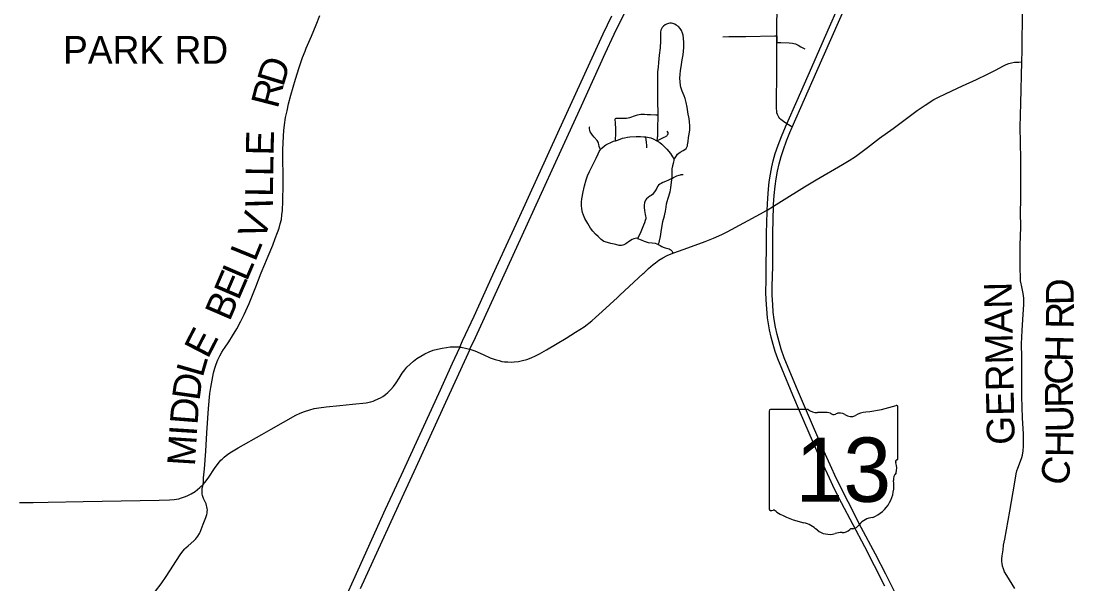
# Model space of a CAD drawing. Extents: x 40529 to 41139, y 15164 to 15584.
# Drawn here: x 40644 to 40708.7, y 15483.8 to 15518.4 of the extents above; entities that cross this region are included whole.
import ezdxf

# ---------------------------------------------------------------- set-up
doc = ezdxf.new("R2010")
doc.units = 0
for name, color, linetype in [('GM_X_County_Road', 7, 'Continuous'), ('GM_X_County_Road_Text', 7, 'Continuous'), ('GM_X_Interstate_Route', 7, 'Continuous'), ('GM_X_State_Route', 7, 'Continuous'), ('GM_X_State_Shield', 7, 'Continuous'), ('GM_X_Township_Road', 7, 'Continuous'), ('GM_X_Township_Road_Text', 7, 'Continuous')]:
    doc.layers.add(name, color=color, linetype=linetype)

msp = doc.modelspace()

# ---------------------------------------------------------------- linework, layer by layer
at = {"layer": 'GM_X_County_Road'}
msp.add_line((40690.484, 15517.074), (40690.486, 15517.482), dxfattribs=at)
for points in [[(40690.486, 15517.482), (40690.499, 15519.736), (40690.48, 15523.462), (40690.467, 15524.818), (40690.446, 15526.018), (40690.447, 15526.289)], [(40690.562, 15512.571), (40690.524, 15512.659), (40690.496, 15512.751), (40690.478, 15512.845), (40690.463, 15513.033), (40690.462, 15513.501), (40690.483, 15515.082), (40690.484, 15517.036), (40690.484, 15517.074)], [(40691.434, 15511.871), (40691.416, 15511.883), (40691.101, 15512.084), (40690.889, 15512.219), (40690.735, 15512.343), (40690.669, 15512.412), (40690.611, 15512.488), (40690.562, 15512.571)], [(40690.285, 15507.02), (40690.287, 15507.118), (40690.319, 15507.677), (40690.374, 15508.235), (40690.437, 15508.698), (40690.52, 15509.158), (40690.624, 15509.613), (40690.748, 15510.063), (40690.89, 15510.508), (40691.083, 15511.034), (40691.294, 15511.552), (40691.434, 15511.871)], [(40697.852, 15483.037), (40697.191, 15484.373), (40696.554, 15485.617), (40695.678, 15487.262), (40694.865, 15488.835), (40694.158, 15490.253), (40693.761, 15491.096), (40693.263, 15492.201), (40692.676, 15493.571), (40691.766, 15495.715), (40691.183, 15497.088), (40690.943, 15497.696), (40690.757, 15498.224), (40690.62, 15498.67), (40690.501, 15499.122), (40690.403, 15499.578), (40690.326, 15500.039), (40690.27, 15500.502), (40690.232, 15500.967), (40690.209, 15501.527), (40690.205, 15502.087), (40690.235, 15503.298), (40690.25, 15505.348), (40690.285, 15507.02)]]:
    msp.add_lwpolyline(points, dxfattribs=at)
at = {"layer": 'GM_X_Interstate_Route'}
for points in [[(40664.908, 15483.496), (40667.468, 15489.094), (40668.323, 15490.959), (40670.372, 15495.457), (40671.634, 15498.213), (40671.653, 15498.253), (40671.967, 15498.932), (40673.396, 15502.073), (40674.83, 15505.21), (40677, 15509.96), (40678.476, 15513.18), (40679.946, 15516.404), (40680.496, 15517.588), (40680.984, 15518.596), (40681.489, 15519.595), (40682.099, 15520.751), (40682.591, 15521.651), (40683.149, 15522.622), (40683.815, 15523.746), (40684.402, 15524.699), (40684.957, 15525.562), (40685.445, 15526.292)], [(40663.802, 15482.52), (40664.754, 15484.647), (40665.607, 15486.512), (40666.451, 15488.381), (40667.424, 15490.498), (40669.714, 15495.498), (40670.562, 15497.365), (40671.003, 15498.331), (40671.012, 15498.352), (40671.181, 15498.722), (40671.88, 15500.248), (40673.036, 15502.793), (40673.858, 15504.569), (40674.592, 15506.181), (40677.027, 15511.523), (40679.237, 15516.354), (40679.823, 15517.622), (40680.352, 15518.712)]]:
    msp.add_lwpolyline(points, dxfattribs=at)
at = {"layer": 'GM_X_State_Route'}
for points in [[(40691.434, 15511.871), (40692.936, 15515.309), (40694.748, 15519.398), (40695.416, 15520.936), (40696.278, 15522.898), (40696.671, 15523.843), (40697.323, 15525.488), (40697.886, 15526.968), (40699.808, 15532.115), (40700.334, 15533.519), (40701.168, 15535.797)], [(40697.124, 15483.649), (40696.496, 15484.899), (40695.887, 15486.053), (40694.461, 15488.777), (40694.038, 15489.606), (40693.72, 15490.28), (40692.952, 15491.977), (40691.95, 15494.284), (40691.468, 15495.394), (40690.788, 15497.029), (40690.549, 15497.634), (40690.393, 15498.072), (40690.255, 15498.516), (40690.135, 15498.964), (40690.033, 15499.417), (40689.967, 15499.783), (40689.918, 15500.151), (40689.865, 15500.706), (40689.832, 15501.263), (40689.82, 15501.728), (40689.827, 15502.473), (40689.861, 15505.361), (40689.893, 15506.665), (40689.897, 15506.776), (40689.924, 15507.502), (40689.966, 15508.058), (40690.018, 15508.52), (40690.088, 15508.98), (40690.176, 15509.436), (40690.263, 15509.797), (40690.394, 15510.243), (40690.572, 15510.772), (40690.769, 15511.294), (40691.019, 15511.896), (40691.101, 15512.084), (40691.728, 15513.517), (40692.627, 15515.565), (40693.42, 15517.354), (40694.508, 15519.826)], [(40690.285, 15507.02), (40690.287, 15507.118), (40690.319, 15507.677), (40690.374, 15508.235), (40690.437, 15508.698), (40690.52, 15509.158), (40690.624, 15509.613), (40690.748, 15510.063), (40690.89, 15510.508), (40691.083, 15511.034), (40691.294, 15511.552), (40691.434, 15511.871)], [(40697.852, 15483.037), (40697.191, 15484.373), (40696.554, 15485.617), (40695.678, 15487.262), (40694.865, 15488.835), (40694.158, 15490.253), (40693.761, 15491.096), (40693.263, 15492.201), (40692.676, 15493.571), (40691.766, 15495.715), (40691.183, 15497.088), (40690.943, 15497.696), (40690.757, 15498.224), (40690.62, 15498.67), (40690.501, 15499.122), (40690.403, 15499.578), (40690.326, 15500.039), (40690.27, 15500.502), (40690.232, 15500.967), (40690.209, 15501.527), (40690.205, 15502.087), (40690.235, 15503.298), (40690.25, 15505.348), (40690.285, 15507.02)]]:
    msp.add_lwpolyline(points, dxfattribs=at)
at = {"layer": 'GM_X_State_Shield'}
for p, q in [((40690.017, 15494.411), (40690.017, 15488.408)), ((40692.412, 15494.515), (40690.095, 15494.515)), ((40697.927, 15491.523), (40697.927, 15494.664)), ((40697.927, 15491.524), (40697.927, 15491.523))]:
    msp.add_line(p, q, dxfattribs=at)
for centre, radius, start, end in [((40690.108, 15494.424), 0.0916, 98.1301, 188.1301), ((40692.963, 15495.212), 0.889, 231.61951, 271.11188), ((40696.18, 15492.681), 1.688, 97.34618, 120.76885), ((40695.11, 15502.7), 8.388, 275.84447, 288.90645), ((40697.84, 15494.677), 0.0881, 351.86209, 97.738), ((40693.258, 15491.144), 3.191, 80.48669, 94.98827), ((40693.983, 15494.455), 0.256, 219.79206, 297.10237), ((40694.359, 15493.761), 0.533, 54.46668, 119.14113), ((40695.047, 15494.713), 0.641, 233.85621, 294.82819), ((40697.907, 15491.292), 0.136, 107.94398, 210.33697), ((40697.04, 15490.895), 0.818, 340.03296, 23.64957), ((40697.833, 15491.511), 0.0942, 289.60381, 7.73413), ((40698.243, 15490.209), 0.595, 136.8065, 186.92959), ((40695.58, 15489.809), 2.098, 292.30889, 8.98584), ((40690.109, 15488.395), 0.0925, 171.95839, 258.30661), ((40690.123, 15489.009), 0.706, 267.33899, 280.60386), ((40690.267, 15488.061), 0.254, 29.74838, 93.27175), ((40693.479, 15493.455), 6.058, 240.41292, 257.1985), ((40691.673, 15485.711), 1.895, 47.18416, 75.83597), ((40695.008, 15487.826), 0.678, 282.87319, 323.27711), ((40696.464, 15486.722), 1.149, 94.40312, 142.57675), ((40693.723, 15488.032), 1.203, 230.70037, 286.29184), ((40694.418, 15485.956), 0.988, 85.69512, 111.20995), ((40694.506, 15487.582), 0.641, 268.77702, 315.54927), ((40695.085, 15487.001), 0.18, 65.75173, 132.64842)]:
    msp.add_arc(centre, radius, start, end, dxfattribs=at)
at = {"layer": 'GM_X_Township_Road'}
msp.add_line((40690.486, 15517.482), (40690.484, 15517.074), dxfattribs=at)
for points in [[(40705.536, 15515.891), (40705.552, 15516.594), (40705.588, 15519.097), (40705.581, 15519.749), (40705.551, 15521.328), (40705.514, 15523.547), (40705.522, 15524.408)], [(40656.486, 15498.19), (40656.549, 15498.289), (40656.806, 15498.664), (40657.047, 15499.044), (40657.298, 15499.467), (40657.558, 15499.934), (40657.765, 15500.349), (40658.059, 15501.018), (40658.478, 15502.043), (40658.809, 15502.916), (40659.026, 15503.444), (40659.238, 15503.947), (40659.514, 15504.618), (40659.67, 15505.027), (40659.81, 15505.386), (40659.902, 15505.651), (40659.98, 15505.921), (40660.047, 15506.197), (40660.08, 15506.474), (40660.104, 15506.754), (40660.132, 15507.313), (40660.145, 15508.339), (40660.143, 15510.481), (40660.171, 15511.321), (40660.193, 15511.661), (40660.234, 15512.02), (40660.303, 15512.462), (40660.391, 15512.873), (40660.478, 15513.304), (40660.623, 15513.845), (40660.92, 15514.825), (40661.137, 15515.539), (40661.346, 15516.149), (40661.505, 15516.556), (40661.564, 15516.725), (40661.897, 15517.469), (40662.189, 15518.159), (40662.402, 15518.733)], [(40684.154, 15509.882), (40684.19, 15509.931), (40684.322, 15510.107), (40684.39, 15510.203), (40684.459, 15510.277), (40684.547, 15510.34), (40684.725, 15510.443), (40684.836, 15510.506), (40684.906, 15510.569), (40684.954, 15510.639), (40684.991, 15510.724), (40685.006, 15510.78), (40685.023, 15510.886), (40685.035, 15510.999), (40685.065, 15511.238), (40685.098, 15511.441), (40685.124, 15511.577), (40685.139, 15511.692), (40685.15, 15511.807), (40685.146, 15511.973), (40685.124, 15512.18), (40685.094, 15512.406), (40685.046, 15512.675), (40684.976, 15513.104), (40684.922, 15513.385), (40684.851, 15513.636), (40684.785, 15513.809), (40684.68, 15514.08), (40684.595, 15514.324), (40684.573, 15514.438), (40684.544, 15514.66), (40684.529, 15514.893), (40684.54, 15515.115), (40684.566, 15515.366), (40684.599, 15515.573), (40684.68, 15516.009), (40684.728, 15516.322), (40684.769, 15516.768), (40684.78, 15517.088), (40684.762, 15517.351), (40684.736, 15517.521), (40684.699, 15517.643), (40684.621, 15517.824), (40684.551, 15517.942), (40684.447, 15518.056), (40684.311, 15518.153), (40684.211, 15518.208), (40684.096, 15518.249), (40684.015, 15518.263), (40683.914, 15518.264), (40683.823, 15518.248), (40683.716, 15518.213), (40683.619, 15518.158), (40683.517, 15518.077), (40683.443, 15517.994), (40683.394, 15517.915), (40683.361, 15517.828), (40683.346, 15517.717), (40683.345, 15517.55), (40683.342, 15517.185), (40683.313, 15516.754), (40683.256, 15516.291), (40683.224, 15515.857), (40683.189, 15515.57), (40683.164, 15515.273), (40683.154, 15515.05), (40683.16, 15514.864), (40683.161, 15514.708), (40683.161, 15514.475), (40683.161, 15514.161), (40683.162, 15513.809), (40683.163, 15513.436), (40683.165, 15512.76), (40683.165, 15512.628), (40683.165, 15512.295), (40683.161, 15512.066), (40683.161, 15511.578), (40683.145, 15511.302), (40683.139, 15511.246), (40683.116, 15511.027)], [(40687.161, 15517.431), (40687.539, 15517.438), (40688.576, 15517.452), (40690.366, 15517.48), (40690.486, 15517.482)], [(40690.484, 15517.074), (40690.541, 15517.074), (40690.73, 15517.073), (40691.253, 15517.05), (40691.442, 15517.032), (40691.535, 15517.015), (40691.626, 15516.989), (40691.713, 15516.955), (40691.798, 15516.915), (40691.963, 15516.821), (40692.208, 15516.689)], [(40689.897, 15506.776), (40690.285, 15507.02), (40690.45, 15507.124), (40690.765, 15507.323), (40692.192, 15508.207), (40692.911, 15508.637), (40694.528, 15509.567), (40694.925, 15509.814), (40695.312, 15510.075), (40696.058, 15510.63), (40696.797, 15511.199), (40697.63, 15511.797), (40698.452, 15512.411), (40699.108, 15512.898), (40699.596, 15513.233), (40700.138, 15513.568), (40700.383, 15513.702), (40700.882, 15513.952), (40701.896, 15514.423), (40702.747, 15514.803), (40703.422, 15515.122), (40703.918, 15515.386), (40704.408, 15515.648), (40704.575, 15515.722), (40704.742, 15515.782), (40704.907, 15515.826), (40705.089, 15515.86), (40705.363, 15515.879), (40705.536, 15515.891)], [(40705.497, 15502.243), (40705.467, 15502.424), (40705.448, 15502.735), (40705.428, 15503.105), (40705.446, 15503.974), (40705.445, 15504.621), (40705.469, 15505.727), (40705.464, 15506.655), (40705.476, 15507.399), (40705.474, 15509.912), (40705.464, 15510.935), (40705.447, 15511.866), (40705.478, 15513.351), (40705.536, 15515.891)], [(40680.568, 15511.039), (40680.576, 15511.129), (40680.6, 15511.414), (40680.604, 15511.649), (40680.592, 15511.872), (40680.58, 15512.006), (40680.564, 15512.165), (40680.55, 15512.328), (40680.556, 15512.366), (40680.574, 15512.398), (40680.622, 15512.416), (40680.937, 15512.425), (40681.258, 15512.433), (40681.457, 15512.461), (40681.582, 15512.502), (40681.687, 15512.541), (40681.916, 15512.628), (40682.123, 15512.668), (40682.233, 15512.677), (40682.359, 15512.665), (40682.525, 15512.656), (40682.716, 15512.644), (40683.045, 15512.632), (40683.165, 15512.628)], [(40679.659, 15510.497), (40679.618, 15510.579), (40679.577, 15510.68), (40679.549, 15510.798), (40679.53, 15510.893), (40679.499, 15510.958), (40679.438, 15511.05), (40679.26, 15511.262), (40679.155, 15511.389), (40679.079, 15511.496), (40679.027, 15511.595), (40678.997, 15511.683), (40678.981, 15511.774), (40678.984, 15511.867), (40678.999, 15511.92)], [(40684.041, 15508.718), (40683.82, 15508.605), (40683.653, 15508.536), (40683.487, 15508.47), (40683.372, 15508.414), (40683.295, 15508.37), (40683.213, 15508.3), (40683.158, 15508.215), (40683.113, 15508.126), (40683.01, 15507.96), (40682.915, 15507.819), (40682.843, 15507.736), (40682.758, 15507.666), (40682.678, 15507.619), (40682.578, 15507.549), (40682.478, 15507.464), (40682.415, 15507.379), (40682.374, 15507.287), (40682.352, 15507.217), (40682.33, 15507.091), (40682.326, 15506.941), (40682.348, 15506.757), (40682.4, 15506.5), (40682.419, 15506.4), (40682.43, 15506.315), (40682.429, 15506.225), (40682.404, 15506.127), (40682.352, 15505.982), (40682.304, 15505.853), (40682.178, 15505.535), (40682.093, 15505.336), (40681.929, 15505.03), (40681.862, 15505.037), (40681.782, 15505.033), (40681.693, 15505.009), (40681.593, 15504.96), (40681.435, 15504.86), (40681.205, 15504.704), (40681.095, 15504.634), (40681.025, 15504.608), (40680.933, 15504.595), (40680.804, 15504.604), (40680.585, 15504.649), (40680.277, 15504.725), (40679.934, 15504.813), (40679.848, 15504.846), (40679.693, 15504.969), (40679.513, 15505.141), (40679.351, 15505.294), (40679.191, 15505.476), (40679.043, 15505.668), (40678.867, 15505.953), (40678.694, 15506.262), (40678.598, 15506.464), (40678.549, 15506.625), (40678.506, 15506.844), (40678.485, 15507.048), (40678.485, 15507.253), (40678.507, 15507.475), (40678.579, 15507.898), (40678.659, 15508.262), (40678.765, 15508.638), (40678.853, 15508.884), (40678.978, 15509.154), (40679.229, 15509.631), (40679.393, 15509.966), (40679.51, 15510.239), (40679.577, 15510.371), (40679.659, 15510.497), (40679.732, 15510.58), (40679.894, 15510.724), (40679.983, 15510.783), (40680.105, 15510.853), (40680.297, 15510.938), (40680.46, 15511.005), (40680.568, 15511.039), (40680.704, 15511.082), (40680.855, 15511.134), (40681.003, 15511.186), (40681.121, 15511.223), (40681.303, 15511.256), (40681.461, 15511.275), (40681.846, 15511.293), (40682.108, 15511.289), (40682.319, 15511.286), (40682.437, 15511.275), (40682.544, 15511.264), (40682.64, 15511.245), (40682.736, 15511.223), (40682.892, 15511.157), (40683.116, 15511.027), (40683.29, 15510.922), (40683.425, 15510.823), (40683.549, 15510.709), (40683.728, 15510.519), (40683.945, 15510.262), (40684.073, 15510.057), (40684.129, 15509.968), (40684.154, 15509.882), (40684.154, 15509.825), (40684.142, 15509.744), (40684.115, 15509.641), (40684.074, 15509.486), (40684.041, 15509.301), (40684.037, 15509.175), (40684.041, 15508.718)], [(40682.492, 15510.611), (40682.5, 15510.758), (40682.486, 15510.922), (40682.437, 15511.275)], [(40683.116, 15511.027), (40683.435, 15511.186), (40683.572, 15511.256), (40683.657, 15511.301), (40683.695, 15511.326), (40683.72, 15511.345), (40683.752, 15511.38), (40683.784, 15511.421), (40683.798, 15511.449), (40683.805, 15511.472), (40683.812, 15511.509), (40683.804, 15511.543), (40683.795, 15511.566), (40683.738, 15511.63)], [(40683.204, 15504.663), (40683.248, 15504.787), (40683.28, 15504.874), (40683.338, 15505.148), (40683.403, 15505.572), (40683.432, 15505.812), (40683.477, 15506.069), (40683.583, 15506.426), (40683.635, 15506.624), (40683.638, 15506.661), (40683.646, 15506.697), (40683.677, 15506.955), (40683.714, 15507.155), (40683.745, 15507.3), (40683.801, 15507.497), (40683.923, 15507.888), (40683.967, 15508.145), (40684.033, 15508.663), (40684.041, 15508.718)], [(40684.041, 15508.718), (40684.137, 15508.78), (40684.259, 15508.847), (40684.351, 15508.884), (40684.481, 15508.928), (40684.562, 15508.946), (40684.61, 15508.954), (40684.658, 15508.957), (40684.725, 15508.954)], [(40684.094, 15504.114), (40684.15, 15504.136), (40685.02, 15504.446), (40686.073, 15504.832), (40686.594, 15505.041), (40687.107, 15505.268), (40687.443, 15505.432), (40689.492, 15506.543), (40689.818, 15506.726), (40689.897, 15506.776)], [(40681.929, 15505.03), (40682.146, 15504.939), (40682.33, 15504.862), (40682.468, 15504.812), (40682.578, 15504.786), (40682.817, 15504.758), (40683.015, 15504.73), (40683.118, 15504.703), (40683.204, 15504.663), (40683.308, 15504.603), (40683.417, 15504.541), (40683.506, 15504.495), (40683.567, 15504.471), (40683.627, 15504.456), (40683.698, 15504.438), (40683.876, 15504.384), (40683.924, 15504.359), (40683.962, 15504.334), (40683.995, 15504.305), (40684.027, 15504.267), (40684.052, 15504.221), (40684.094, 15504.114)], [(40665.683, 15495.025), (40665.77, 15495.053), (40665.999, 15495.16), (40666.137, 15495.231), (40666.28, 15495.318), (40666.433, 15495.428), (40666.576, 15495.549), (40666.776, 15495.749), (40666.938, 15495.923), (40667.1, 15496.14), (40667.275, 15496.428), (40667.476, 15496.74), (40667.62, 15496.955), (40667.756, 15497.108), (40667.948, 15497.291), (40668.161, 15497.483), (40668.374, 15497.641), (40668.609, 15497.798), (40668.856, 15497.931), (40669.12, 15498.054), (40669.367, 15498.152), (40669.644, 15498.229), (40669.915, 15498.29), (40670.189, 15498.33), (40670.42, 15498.353), (40670.68, 15498.365), (40670.878, 15498.364), (40670.978, 15498.358), (40671.012, 15498.352), (40671.089, 15498.339), (40671.182, 15498.322), (40671.349, 15498.288), (40671.52, 15498.25), (40671.634, 15498.213), (40671.741, 15498.178), (40671.926, 15498.108), (40672.439, 15497.886), (40672.878, 15497.688), (40673.189, 15497.575), (40673.416, 15497.516), (40673.598, 15497.471), (40673.761, 15497.447), (40673.953, 15497.432), (40674.161, 15497.427), (40674.353, 15497.437), (40674.605, 15497.467), (40674.861, 15497.513), (40675.132, 15497.591), (40675.395, 15497.691), (40675.65, 15497.808), (40675.899, 15497.938), (40676.331, 15498.177), (40676.997, 15498.567), (40677.545, 15498.892), (40678.112, 15499.257), (40678.64, 15499.603), (40679.117, 15499.971), (40679.343, 15500.158), (40679.759, 15500.536), (40680.706, 15501.4), (40680.839, 15501.531), (40681.704, 15502.336), (40682.264, 15502.865), (40682.342, 15502.919), (40682.609, 15503.171), (40682.878, 15503.418), (40683.024, 15503.532), (40683.243, 15503.697), (40683.485, 15503.842), (40683.751, 15503.979), (40684.094, 15504.114)], [(40705.105, 15483.508), (40704.615, 15484.295), (40704.481, 15484.535), (40704.407, 15484.702), (40704.354, 15484.876), (40704.322, 15485.056), (40704.314, 15485.147), (40704.312, 15485.239), (40704.316, 15485.33), (40704.333, 15485.513), (40704.386, 15485.882), (40704.421, 15486.157), (40704.487, 15486.525), (40704.796, 15488.264), (40705.107, 15490.04), (40705.201, 15490.553), (40705.241, 15490.731), (40705.295, 15490.898), (40705.457, 15491.328), (40705.546, 15491.555), (40705.586, 15491.693), (40705.625, 15491.964), (40705.638, 15492.247), (40705.65, 15492.719), (40705.64, 15492.99), (40705.591, 15494.002), (40705.546, 15495.309), (40705.537, 15496.602), (40705.537, 15497.71), (40705.527, 15498.556), (40705.551, 15499.375), (40705.596, 15500.041), (40705.659, 15500.957), (40705.663, 15501.328), (40705.64, 15501.516), (40705.606, 15501.738), (40705.512, 15502.153), (40705.497, 15502.243)], [(40655.241, 15489.903), (40655.257, 15490.03), (40655.264, 15490.125), (40655.269, 15490.31), (40655.317, 15490.867), (40655.405, 15491.945), (40655.455, 15493.084), (40655.558, 15494.571), (40655.649, 15495.497), (40655.7, 15495.865), (40655.785, 15496.32), (40655.882, 15496.773), (40655.954, 15497.041), (40656.039, 15497.306), (40656.137, 15497.566), (40656.253, 15497.817), (40656.391, 15498.042), (40656.486, 15498.19)], [(40655.241, 15489.903), (40655.426, 15490.115), (40655.596, 15490.34), (40655.945, 15490.89), (40656.155, 15491.193), (40656.334, 15491.398), (40656.4, 15491.463), (40656.538, 15491.586), (40656.755, 15491.757), (40656.988, 15491.913), (40657.385, 15492.152), (40658.845, 15492.979), (40659.413, 15493.3), (40660.931, 15494.151), (40661.192, 15494.278), (40661.46, 15494.393), (40661.795, 15494.496), (40662.066, 15494.561), (40662.338, 15494.61), (40662.799, 15494.67), (40663.637, 15494.749), (40664.41, 15494.827), (40665.262, 15494.921), (40665.539, 15494.977), (40665.683, 15495.025)], [(40643.954, 15488.787), (40644.792, 15488.788), (40645.725, 15488.806), (40647.868, 15488.847), (40652.529, 15488.928), (40653.176, 15488.951), (40653.455, 15488.977), (40653.734, 15489.022), (40653.917, 15489.067), (40654.097, 15489.129), (40654.264, 15489.2), (40654.505, 15489.324), (40654.745, 15489.472), (40654.897, 15489.583), (40655.041, 15489.705), (40655.241, 15489.903)], [(40652.312, 15483.338), (40652.649, 15483.784), (40652.971, 15484.242), (40653.834, 15485.57), (40653.995, 15485.796), (40654.11, 15485.937), (40654.173, 15486.003), (40654.312, 15486.124), (40654.661, 15486.432), (40654.796, 15486.565), (40654.91, 15486.714), (40655.01, 15486.873), (40655.051, 15486.957), (40655.124, 15487.13), (40655.248, 15487.466), (40655.406, 15487.866), (40655.464, 15488.046), (40655.483, 15488.139), (40655.494, 15488.234), (40655.496, 15488.329), (40655.488, 15488.424), (40655.473, 15488.519), (40655.449, 15488.611), (40655.417, 15488.7), (40655.261, 15489.038), (40655.205, 15489.212), (40655.187, 15489.301), (40655.176, 15489.392), (40655.172, 15489.482), (40655.176, 15489.573), (40655.186, 15489.664), (40655.241, 15489.903)]]:
    msp.add_lwpolyline(points, dxfattribs=at)

# ---------------------------------------------------------------- texts
at = {"layer": 'GM_X_County_Road_Text'}
msp.add_text('PARK RD', height=1.7063, rotation=359.9994, dxfattribs=at).set_placement((40646.632, 15515.772))
at = {"layer": 'GM_X_State_Shield'}
msp.add_text('13', height=3.9551, dxfattribs=at).set_placement((40691.627, 15488.831))
at = {"layer": 'GM_X_Township_Road_Text'}
for s, height, rotation, p in [('D', 1.706, 72.93368, (40660.154, 15514.3)), ('R', 1.706, 75.55859, (40659.811, 15512.963)), ('E', 1.706, 88.81703, (40659.564, 15510.121)), ('L', 1.706, 89.05812, (40659.543, 15508.847)), ('L', 1.706, 89.03136, (40659.521, 15507.57)), ('I', 1.706, 91.63689, (40659.541, 15506.89)), ('V', 1.706, 70.86948, (40658.949, 15504.818)), ('L', 1.706, 67.83913, (40658.433, 15503.546)), ('L', 1.706, 66.80848, (40657.918, 15502.342)), ('E', 1.706, 66.72473, (40657.412, 15501.167)), ('GERMAN', 1.7063, 91.08439, (40705.103, 15492.355)), ('D', 1.706, 91.47799, (40708.739, 15500.945)), ('B', 1.706, 66.7235, (40656.858, 15499.88)), ('R', 1.706, 89.06596, (40708.716, 15499.465)), ('E', 1.706, 62.64526, (40655.521, 15497.575)), ('H', 1.706, 88.63017, (40708.666, 15497.421)), ('L', 1.706, 73.96865, (40655.201, 15496.431)), ('C', 1.706, 89.71117, (40708.659, 15496.028)), ('D', 1.706, 81.9044, (40655.003, 15495.006)), ('R', 1.706, 90.9914, (40708.683, 15494.637)), ('D', 1.706, 85.53675, (40654.889, 15493.537)), ('U', 1.706, 91.25059, (40708.716, 15493.138)), ('I', 1.706, 86.34428, (40654.845, 15492.844)), ('M', 1.706, 86.39713, (40654.729, 15490.997)), ('H', 1.706, 89.30361, (40708.698, 15491.573)), ('C', 1.706, 72.05504, (40708.176, 15489.689))]:
    msp.add_text(s, height=height, rotation=rotation, dxfattribs=at).set_placement(p)

doc.saveas('drawing.dxf')
